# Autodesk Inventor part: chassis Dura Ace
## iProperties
Created: 2011-11
Part Number: chassis Dura Ace
Document SubType Name: Modeling
Designer: Laur
Density: 1 g/cm^3
Mass: 2.29452 g
Surface Area: 25.8387 cm^2
Volume: 2.29452 cm^3
Author: Laur
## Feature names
1. Extrusion1
2. Extrusion2
3. Extrusion3
4. Extrusion4
5. Extrusion5
6. Extrusion6
7. Extrusion7
8. Extrusion8
